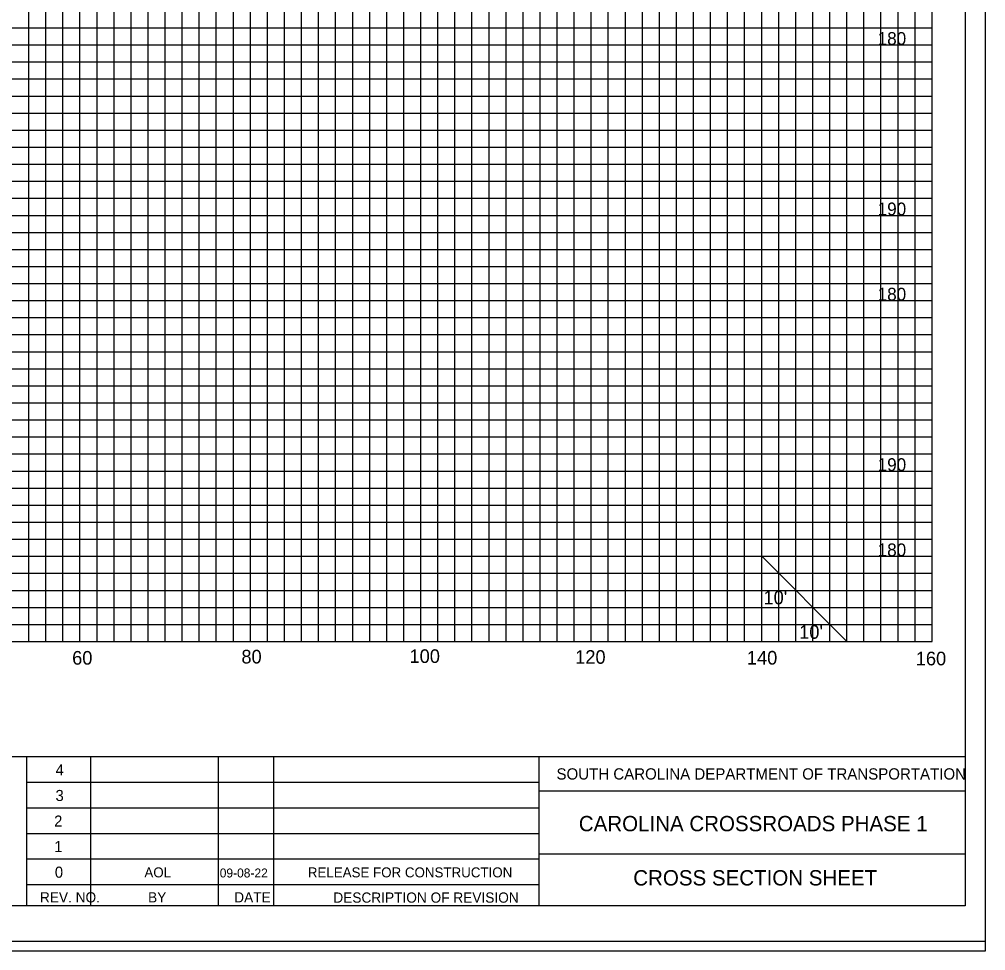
# Model space of a CAD drawing. Extents: x 967 to 1326, y 964 to 2584.
# Drawn here: x 1212.9 to 1326.3, y 2363.7 to 2473 of the extents above; entities that cross this region are included whole.
import ezdxf

# ---------------------------------------------------------------- set-up
doc = ezdxf.new("R2010")
doc.units = 0
for name, color, linetype in [('Default', 7, 'Continuous'), ('RD_GPK_XS_Cell', 7, 'Continuous'), ('RD_SHT_Misc1', 7, 'Continuous'), ('RD_XS_ExGround', 7, 'Continuous'), ('RD_XS_ExPaveRet', 7, 'Continuous'), ('RD_XS_Misc_Line', 7, 'Continuous'), ('RD_XS_TX_Elev_EX', 7, 'Continuous')]:
    doc.layers.add(name, color=color, linetype=linetype)

msp = doc.modelspace()

# ---------------------------------------------------------------- linework, layer by layer
at = {"layer": 'RD_GPK_XS_Cell'}
for p, q in [((1220, 2400), (1220, 2570)), ((1230, 2400), (1230, 2570)), ((1240, 2400), (1240, 2570)), ((1250, 2400), (1250, 2570)), ((1260, 2400), (1260, 2570)), ((1270, 2400), (1270, 2570)), ((1280, 2400), (1280, 2570)), ((1290, 2400), (1290, 2570)), ((1300, 2400), (1300, 2570)), ((1310, 2400), (1310, 2570)), ((1320, 2400), (1320, 2570)), ((1000, 2470), (1320, 2470)), ((1000, 2460), (1320, 2460)), ((1000, 2450), (1320, 2450)), ((1000, 2440), (1320, 2440)), ((1000, 2430), (1320, 2430)), ((1000, 2420), (1320, 2420)), ((1000, 2410), (1320, 2410)), ((1000, 2400), (1320, 2400))]:
    msp.add_line(p, q, dxfattribs=at)
at = {"layer": 'RD_XS_ExGround'}
for p, q in [((1214, 2400), (1214, 2570)), ((1216, 2400), (1216, 2570)), ((1218, 2400), (1218, 2570)), ((1222, 2400), (1222, 2570)), ((1224, 2400), (1224, 2570)), ((1226, 2400), (1226, 2570)), ((1228, 2400), (1228, 2570)), ((1232, 2400), (1232, 2570)), ((1234, 2400), (1234, 2570)), ((1236, 2400), (1236, 2570)), ((1238, 2400), (1238, 2570)), ((1242, 2400), (1242, 2570)), ((1244, 2400), (1244, 2570)), ((1246, 2400), (1246, 2570)), ((1248, 2400), (1248, 2570)), ((1252, 2400), (1252, 2570)), ((1254, 2400), (1254, 2570)), ((1256, 2400), (1256, 2570)), ((1258, 2400), (1258, 2570)), ((1262, 2400), (1262, 2570)), ((1264, 2400), (1264, 2570)), ((1266, 2400), (1266, 2570)), ((1268, 2400), (1268, 2570)), ((1272, 2400), (1272, 2570)), ((1274, 2400), (1274, 2570)), ((1276, 2400), (1276, 2570)), ((1278, 2400), (1278, 2570)), ((1282, 2400), (1282, 2570)), ((1284, 2400), (1284, 2570)), ((1286, 2400), (1286, 2570)), ((1288, 2400), (1288, 2570)), ((1292, 2400), (1292, 2570)), ((1294, 2400), (1294, 2570)), ((1296, 2400), (1296, 2570)), ((1298, 2400), (1298, 2570)), ((1302, 2400), (1302, 2570)), ((1304, 2400), (1304, 2570)), ((1306, 2400), (1306, 2570)), ((1308, 2400), (1308, 2570)), ((1312, 2400), (1312, 2570)), ((1314, 2400), (1314, 2570)), ((1316, 2400), (1316, 2570)), ((1318, 2400), (1318, 2570)), ((1000, 2472), (1320, 2472)), ((1000, 2468), (1320, 2468)), ((1000, 2466), (1320, 2466)), ((1000, 2464), (1320, 2464)), ((1000, 2462), (1320, 2462)), ((1000, 2458), (1320, 2458)), ((1000, 2456), (1320, 2456)), ((1000, 2454), (1320, 2454)), ((1000, 2452), (1320, 2452)), ((1000, 2448), (1320, 2448)), ((1000, 2446), (1320, 2446)), ((1000, 2444), (1320, 2444)), ((1000, 2442), (1320, 2442)), ((1000, 2438), (1320, 2438)), ((1000, 2436), (1320, 2436)), ((1000, 2434), (1320, 2434)), ((1000, 2432), (1320, 2432)), ((1000, 2428), (1320, 2428)), ((1000, 2426), (1320, 2426)), ((1000, 2424), (1320, 2424)), ((1000, 2422), (1320, 2422)), ((1000, 2418), (1320, 2418)), ((1000, 2416), (1320, 2416)), ((1000, 2414), (1320, 2414)), ((1000, 2412), (1320, 2412)), ((1000, 2408), (1320, 2408)), ((1000, 2406), (1320, 2406)), ((1000, 2404), (1320, 2404)), ((1000, 2402), (1320, 2402))]:
    msp.add_line(p, q, dxfattribs=at)
at = {"layer": 'RD_XS_ExPaveRet'}
for points in [[(967.41, 2363.72), (1326.28, 2363.72), (1326.28, 2583.72), (967.41, 2583.72)], [(988.52, 2364.84), (1326.28, 2364.84), (1326.28, 2582.6), (988.52, 2582.6)]]:
    msp.add_lwpolyline(points, close=True, dxfattribs=at)
at = {"layer": 'RD_XS_Misc_Line'}
msp.add_line((1300, 2410), (1310, 2400), dxfattribs=at)
at = {"layer": 'RD_XS_TX_Elev_EX'}
for p, q in [((1323.89, 2578.46), (1323.89, 2368.98)), ((996.11, 2386.49), (1323.89, 2386.49)), ((1213.76, 2368.94), (1213.76, 2386.49)), ((1221.26, 2368.95), (1221.26, 2386.48)), ((1236.26, 2368.95), (1236.26, 2386.48)), ((1242.76, 2368.95), (1242.76, 2386.48)), ((1273.88, 2368.98), (1273.88, 2386.49)), ((1213.76, 2383.48), (1273.88, 2383.48)), ((1323.93, 2382.43), (1273.88, 2382.43)), ((1213.76, 2380.48), (1273.88, 2380.48)), ((1213.76, 2377.48), (1273.88, 2377.48)), ((1323.89, 2375.04), (1273.88, 2375.04)), ((1213.76, 2374.48), (1273.88, 2374.48)), ((1213.76, 2371.48), (1273.88, 2371.48)), ((1323.89, 2368.98), (996.11, 2368.98))]:
    msp.add_line(p, q, dxfattribs=at)

# ---------------------------------------------------------------- texts
at = {"layer": 'Default'}
for s, p in [('180', (1313.61, 2470)), ('190', (1313.61, 2450)), ('180', (1313.61, 2440)), ('190', (1313.61, 2420)), ('180', (1313.61, 2410))]:
    msp.add_text(s, height=1.5, dxfattribs=at).set_placement(p)
at = {"layer": 'RD_SHT_Misc1'}
for s, height, p in [('AOL', 1.17, (1227.56, 2372.32)), ('09-08-22', 1.053, (1236.4, 2372.31)), ('RELEASE FOR CONSTRUCTION', 1.17, (1246.74, 2372.32))]:
    msp.add_text(s, height=height, dxfattribs=at).set_placement(p)
at = {"layer": 'RD_XS_Misc_Line'}
for s, height, p in [("10'", 1.6, (1300.21, 2404.36)), ("10'", 1.6, (1304.4, 2400.32)), ('60', 1.6, (1219.08, 2397.28)), ('80', 1.6, (1238.94, 2397.42)), ('100', 1.6, (1258.67, 2397.48)), ('120', 1.6, (1278.11, 2397.38)), ('140', 1.6, (1298.26, 2397.29)), ('160', 1.6, (1318.08, 2397.2)), ('4', 1.3, (1217.13, 2384.28)), ('SOUTH CAROLINA DEPARTMENT OF TRANSPORTATION', 1.32, (1275.92, 2383.8)), ('3', 1.3, (1217.13, 2381.28)), ('2', 1.3, (1216.97, 2378.28)), ('1', 1.3, (1216.97, 2375.28)), ('0', 1.3, (1217.05, 2372.28)), ('REV. NO.', 1.2, (1215.3, 2369.38)), ('BY', 1.2, (1227.99, 2369.38)), ('DATE', 1.2, (1238.1, 2369.38)), ('DESCRIPTION OF REVISION', 1.2, (1249.73, 2369.35))]:
    msp.add_text(s, height=height, dxfattribs=at).set_placement(p)
for s, p in [('CAROLINA CROSSROADS PHASE 1', (1278.54, 2377.73)), ('CROSS SECTION SHEET', (1284.93, 2371.37))]:
    msp.add_text(s, height=1.8, rotation=0, dxfattribs=at).set_placement(p)

doc.saveas('drawing.dxf')
